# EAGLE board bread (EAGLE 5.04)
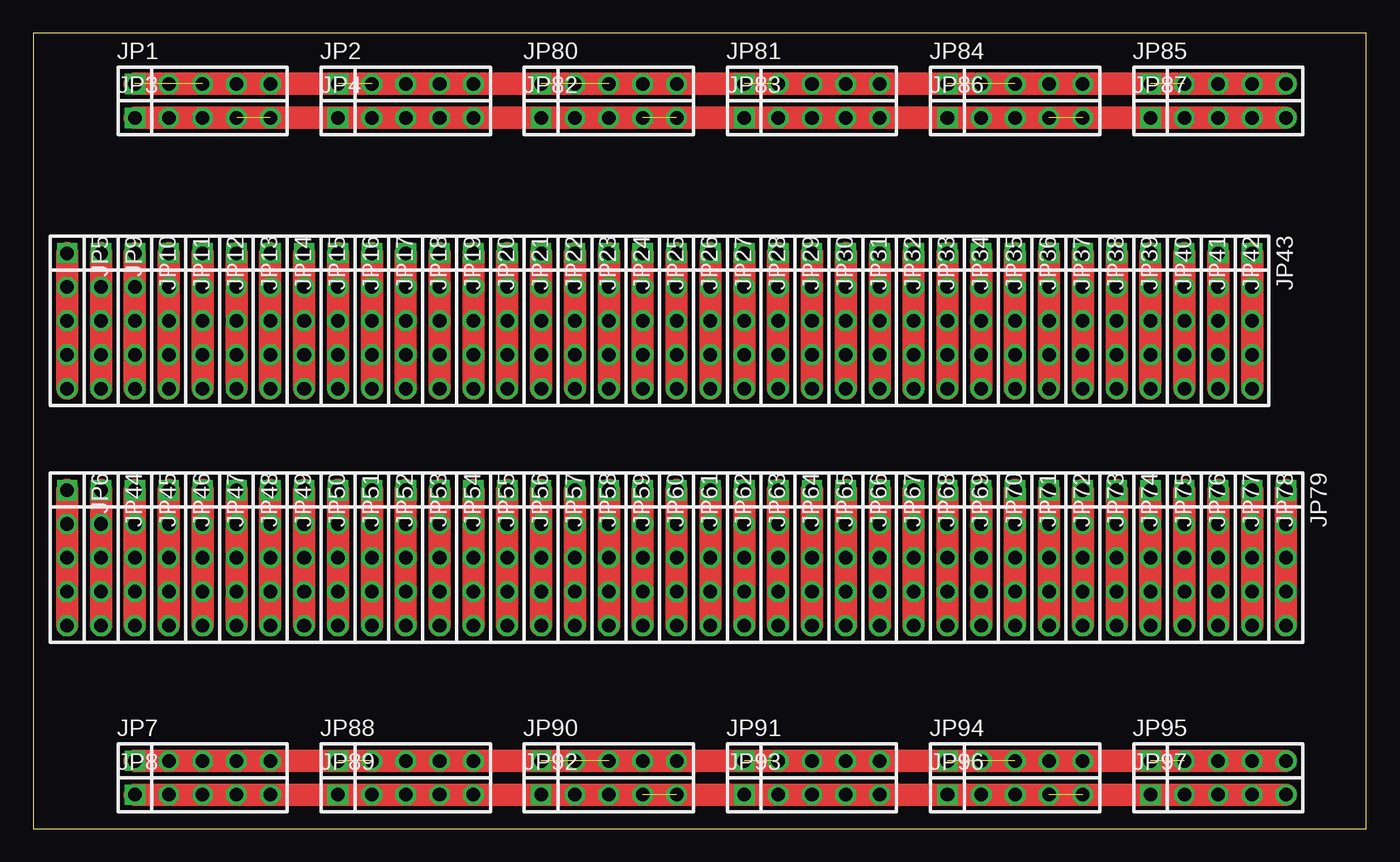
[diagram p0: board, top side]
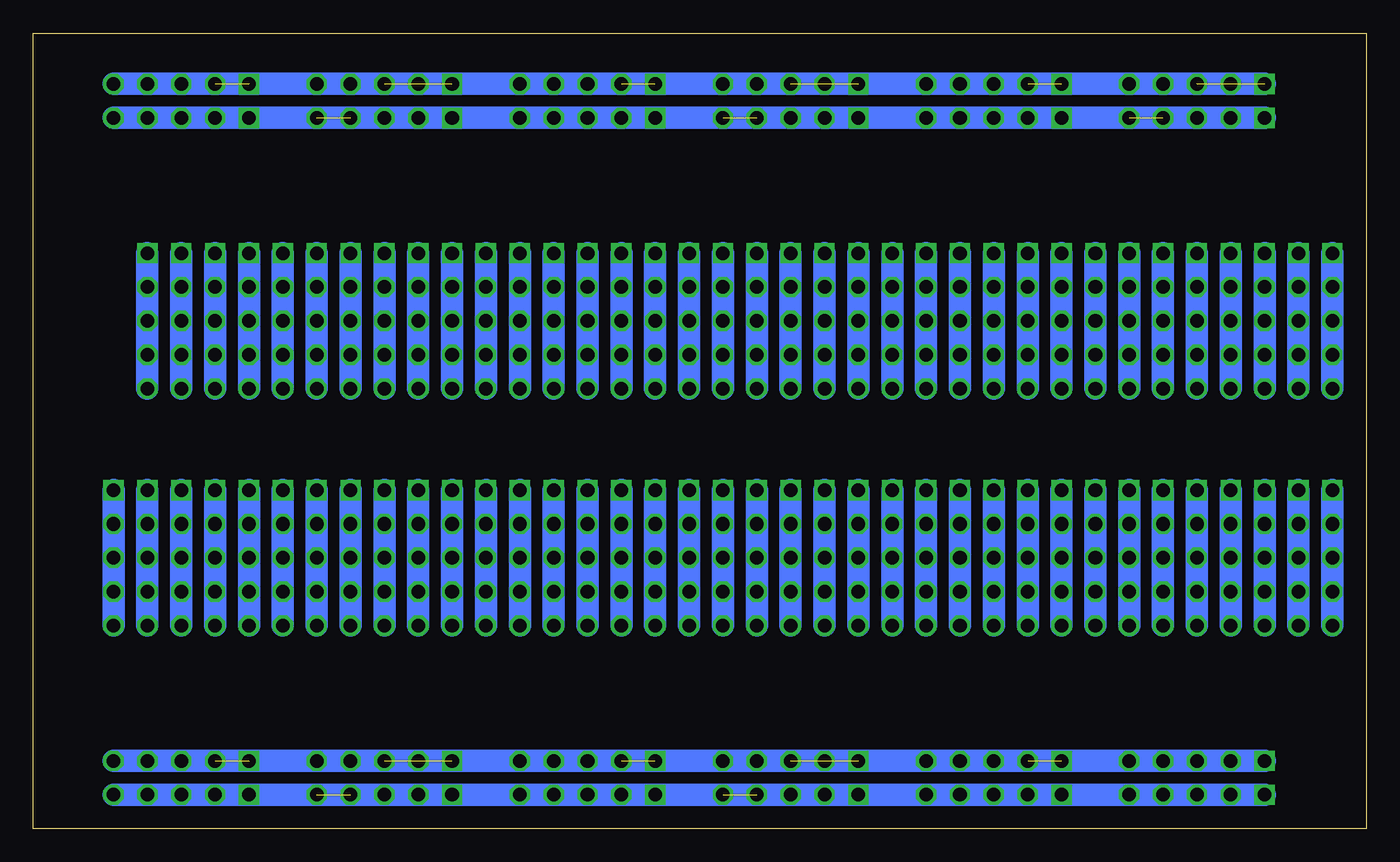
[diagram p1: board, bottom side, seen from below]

Size 100 x 59.68 mm. Coordinates in mm from the lower left corner, seen from the top.
Outline: 0,0 100,0 100,59.68 0,59.68 0,0
Copper layers (1*16): Top 0.035mm / dielectric 1.5mm / Bottom 0.035mm
Design rules "default": minimum track width 10mil, minimum drill 24mil, track to track 8mil, track to pad 8mil, pad to pad 8mil, via to via 8mil, smd to smd 8mil, copper to edge 40mil, drill to drill 8mil, minimum pad ring 10mil, minimum via ring 8mil, stop-mask expansion 4mil, vias tented up to drill 0mil, thermal gap 10mil

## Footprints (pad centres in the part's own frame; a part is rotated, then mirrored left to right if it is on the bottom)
1X05 = drill 1.016 square: 1 -5.08,0 | drill 1.016 octagon: 2 -2.54,0; 3 0,0; 4 2.54,0; 5 5.08,0

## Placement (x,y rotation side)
JP1  [1X05]  12.7,55.88 0 top
JP2  [1X05]  27.94,55.88 0 top
JP3  [1X05]  12.7,53.34 0 top
JP4  [1X05]  27.94,53.34 0 top
JP5  [1X05]  2.54,38.1 270 top
JP6  [1X05]  2.54,20.32 270 top
JP7  [1X05]  12.7,5.08 0 top
JP8  [1X05]  12.7,2.54 0 top
JP9  [1X05]  5.08,38.1 270 top
JP10  [1X05]  7.62,38.1 270 top
JP11  [1X05]  10.16,38.1 270 top
JP12  [1X05]  12.7,38.1 270 top
JP13  [1X05]  15.24,38.1 270 top
JP14  [1X05]  17.78,38.1 270 top
JP15  [1X05]  20.32,38.1 270 top
JP16  [1X05]  22.86,38.1 270 top
JP17  [1X05]  25.4,38.1 270 top
JP18  [1X05]  27.94,38.1 270 top
JP19  [1X05]  30.48,38.1 270 top
JP20  [1X05]  33.02,38.1 270 top
JP21  [1X05]  35.56,38.1 270 top
JP22  [1X05]  38.1,38.1 270 top
JP23  [1X05]  40.64,38.1 270 top
JP24  [1X05]  43.18,38.1 270 top
JP25  [1X05]  45.72,38.1 270 top
JP26  [1X05]  48.26,38.1 270 top
JP27  [1X05]  50.8,38.1 270 top
JP28  [1X05]  53.34,38.1 270 top
JP29  [1X05]  55.88,38.1 270 top
JP30  [1X05]  58.42,38.1 270 top
JP31  [1X05]  60.96,38.1 270 top
JP32  [1X05]  63.5,38.1 270 top
JP33  [1X05]  66.04,38.1 270 top
JP34  [1X05]  68.58,38.1 270 top
JP35  [1X05]  71.12,38.1 270 top
JP36  [1X05]  73.66,38.1 270 top
JP37  [1X05]  76.2,38.1 270 top
JP38  [1X05]  78.74,38.1 270 top
JP39  [1X05]  81.28,38.1 270 top
JP40  [1X05]  83.82,38.1 270 top
JP41  [1X05]  86.36,38.1 270 top
JP42  [1X05]  88.9,38.1 270 top
JP43  [1X05]  91.44,38.1 270 top
JP44  [1X05]  5.08,20.32 270 top
JP45  [1X05]  7.62,20.32 270 top
JP46  [1X05]  10.16,20.32 270 top
JP47  [1X05]  12.7,20.32 270 top
JP48  [1X05]  15.24,20.32 270 top
JP49  [1X05]  17.78,20.32 270 top
JP50  [1X05]  20.32,20.32 270 top
JP51  [1X05]  22.86,20.32 270 top
JP52  [1X05]  25.4,20.32 270 top
JP53  [1X05]  27.94,20.32 270 top
JP54  [1X05]  30.48,20.32 270 top
JP55  [1X05]  33.02,20.32 270 top
JP56  [1X05]  35.56,20.32 270 top
JP57  [1X05]  38.1,20.32 270 top
JP58  [1X05]  40.64,20.32 270 top
JP59  [1X05]  43.18,20.32 270 top
JP60  [1X05]  45.72,20.32 270 top
JP61  [1X05]  48.26,20.32 270 top
JP62  [1X05]  50.8,20.32 270 top
JP63  [1X05]  53.34,20.32 270 top
JP64  [1X05]  55.88,20.32 270 top
JP65  [1X05]  58.42,20.32 270 top
JP66  [1X05]  60.96,20.32 270 top
JP67  [1X05]  63.5,20.32 270 top
JP68  [1X05]  66.04,20.32 270 top
JP69  [1X05]  68.58,20.32 270 top
JP70  [1X05]  71.12,20.32 270 top
JP71  [1X05]  73.66,20.32 270 top
JP72  [1X05]  76.2,20.32 270 top
JP73  [1X05]  78.74,20.32 270 top
JP74  [1X05]  81.28,20.32 270 top
JP75  [1X05]  83.82,20.32 270 top
JP76  [1X05]  86.36,20.32 270 top
JP77  [1X05]  88.9,20.32 270 top
JP78  [1X05]  91.44,20.32 270 top
JP79  [1X05]  93.98,20.32 270 top
JP80  [1X05]  43.18,55.88 0 top
JP81  [1X05]  58.42,55.88 0 top
JP82  [1X05]  43.18,53.34 0 top
JP83  [1X05]  58.42,53.34 0 top
JP84  [1X05]  73.66,55.88 0 top
JP85  [1X05]  88.9,55.88 0 top
JP86  [1X05]  73.66,53.34 0 top
JP87  [1X05]  88.9,53.34 0 top
JP88  [1X05]  27.94,5.08 0 top
JP89  [1X05]  27.94,2.54 0 top
JP90  [1X05]  43.18,5.08 0 top
JP91  [1X05]  58.42,5.08 0 top
JP92  [1X05]  43.18,2.54 0 top
JP93  [1X05]  58.42,2.54 0 top
JP94  [1X05]  73.66,5.08 0 top
JP95  [1X05]  88.9,5.08 0 top
JP96  [1X05]  73.66,2.54 0 top
JP97  [1X05]  88.9,2.54 0 top

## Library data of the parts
JP1-JP97 = pinhead(2)

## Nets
N$1: JP1.1 JP1.2 JP1.3
N$2: JP2.1 JP2.2
N$3: JP3.4 JP3.5
N$76: JP80.1 JP80.2 JP80.3
N$77: JP81.1 JP81.2
N$78: JP82.4 JP82.5
N$80: JP84.1 JP84.2 JP84.3
N$81: JP85.1 JP85.2
N$82: JP86.4 JP86.5
N$84: JP88.1 JP88.2
N$86: JP90.1 JP90.2 JP90.3
N$87: JP91.1 JP91.2
N$88: JP92.4 JP92.5
N$90: JP94.1 JP94.2 JP94.3
N$91: JP95.1 JP95.2
N$92: JP96.4 JP96.5

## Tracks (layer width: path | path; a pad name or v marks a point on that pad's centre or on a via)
N$1  (2 unrouted)
N$2  (1 unrouted)
N$3  (1 unrouted)
N$4
  Top 1.676: 2.54,33.02 2.54,43.18
N$5
  Top 1.676: 5.08,33.02 5.08,43.18
N$6
  Top 1.676: 7.62,33.02 7.62,43.18
N$7
  Top 1.676: 91.44,33.02 91.44,43.18
N$8
  Top 1.676: 88.9,33.02 88.9,43.18
N$9
  Top 1.676: 86.36,33.02 86.36,43.18
N$10
  Top 1.676: 83.82,33.02 83.82,43.18
N$11
  Top 1.676: 81.28,33.02 81.28,43.18
N$12
  Top 1.676: 78.74,33.02 78.74,43.18
N$13
  Top 1.676: 76.2,33.02 76.2,43.18
N$14
  Top 1.676: 73.66,33.02 73.66,43.18
N$15
  Top 1.676: 71.12,33.02 71.12,43.18
N$16
  Top 1.676: 68.58,33.02 68.58,43.18
N$17
  Top 1.676: 66.04,33.02 66.04,43.18
N$18
  Top 1.676: 63.5,33.02 63.5,43.18
N$19
  Top 1.676: 60.96,33.02 60.96,43.18
N$20
  Top 1.676: 58.42,33.02 58.42,43.18
N$21
  Top 1.676: 55.88,33.02 55.88,43.18
N$22
  Top 1.676: 53.34,33.02 53.34,43.18
N$23
  Top 1.676: 50.8,33.02 50.8,43.18
N$24
  Top 1.676: 48.26,33.02 48.26,43.18
N$25
  Top 1.676: 45.72,33.02 45.72,43.18
N$26
  Top 1.676: 43.18,33.02 43.18,43.18
N$27
  Top 1.676: 40.64,33.02 40.64,43.18
N$28
  Top 1.676: 38.1,33.02 38.1,43.18
N$29
  Top 1.676: 35.56,33.02 35.56,43.18
N$30
  Top 1.676: 33.02,33.02 33.02,43.18
N$31
  Top 1.676: 30.48,33.02 30.48,43.18
N$32
  Top 1.676: 27.94,33.02 27.94,43.18
N$33
  Top 1.676: 25.4,33.02 25.4,43.18
N$34
  Top 1.676: 22.86,33.02 22.86,43.18
N$35
  Top 1.676: 20.32,33.02 20.32,43.18
N$36
  Top 1.676: 17.78,33.02 17.78,43.18
N$37
  Top 1.676: 15.24,33.02 15.24,43.18
N$38
  Top 1.676: 12.7,33.02 12.7,43.18
N$39
  Top 1.676: 10.16,33.02 10.16,43.18
N$40
  Top 1.676: 5.08,15.24 5.08,25.4 | 93.98,55.88 83.82,55.88 | 83.82,53.34 93.98,53.34 | 68.58,53.34 78.74,53.34 | 78.74,55.88 68.58,55.88 | 2.54,25.4 2.54,15.24
N$41
  Top 1.676: 93.98,15.24 93.98,25.4
N$42
  Top 1.676: 91.44,15.24 91.44,25.4
N$43
  Top 1.676: 88.9,15.24 88.9,25.4
N$44
  Top 1.676: 86.36,15.24 86.36,25.4
N$45
  Top 1.676: 83.82,15.24 83.82,25.4
N$46
  Top 1.676: 81.28,15.24 81.28,25.4
N$47
  Top 1.676: 78.74,15.24 78.74,25.4
N$48
  Top 1.676: 76.2,15.24 76.2,25.4
N$49
  Top 1.676: 73.66,15.24 73.66,25.4
N$50
  Top 1.676: 71.12,15.24 71.12,25.4
N$51
  Top 1.676: 68.58,15.24 68.58,25.4
N$52
  Top 1.676: 66.04,15.24 66.04,25.4
N$53
  Top 1.676: 63.5,15.24 63.5,25.4
N$54
  Top 1.676: 60.96,15.24 60.96,25.4
N$55
  Top 1.676: 58.42,15.24 58.42,25.4
N$56
  Top 1.676: 55.88,15.24 55.88,25.4
N$57
  Top 1.676: 53.34,15.24 53.34,25.4
N$58
  Top 1.676: 50.8,15.24 50.8,25.4
N$59
  Top 1.676: 48.26,15.24 48.26,25.4
N$60
  Top 1.676: 45.72,15.24 45.72,25.4
N$61
  Top 1.676: 43.18,15.24 43.18,25.4
N$62
  Top 1.676: 40.64,15.24 40.64,25.4
N$63
  Top 1.676: 38.1,15.24 38.1,25.4
N$64
  Top 1.676: 35.56,15.24 35.56,25.4
N$65
  Top 1.676: 33.02,15.24 33.02,25.4
N$66
  Top 1.676: 30.48,15.24 30.48,25.4
N$67
  Top 1.676: 27.94,15.24 27.94,25.4
N$68
  Top 1.676: 25.4,15.24 25.4,25.4
N$69
  Top 1.676: 22.86,15.24 22.86,25.4
N$70
  Top 1.676: 20.32,15.24 20.32,25.4
N$71
  Top 1.676: 17.78,15.24 17.78,25.4
N$72
  Top 1.676: 15.24,15.24 15.24,25.4
N$73
  Top 1.676: 12.7,15.24 12.7,25.4
N$74
  Top 1.676: 10.16,15.24 10.16,25.4
N$75
  Top 1.676: 7.62,15.24 7.62,25.4
N$76  (2 unrouted)
N$77  (1 unrouted)
N$78  (1 unrouted)
N$79
  Top 1.676: 63.5,55.88 53.34,55.88 | 53.34,53.34 63.5,53.34 | 38.1,53.34 48.26,53.34 | 48.26,55.88 38.1,55.88
N$80  (2 unrouted)
N$81  (1 unrouted)
N$82  (1 unrouted)
N$83
  Top 1.676: 33.02,55.88 22.86,55.88 | 22.86,53.34 33.02,53.34 | 7.62,53.34 17.78,53.34 | 17.78,55.88 7.62,55.88
N$84  (1 unrouted)
N$85
  Top 1.676: 68.58,2.54 78.74,2.54 | 78.74,5.08 68.58,5.08 | 93.98,5.08 83.82,5.08 | 83.82,2.54 93.98,2.54
N$86  (2 unrouted)
N$87  (1 unrouted)
N$88  (1 unrouted)
N$89
  Top 1.676: 63.5,5.08 53.34,5.08 | 53.34,2.54 63.5,2.54 | 38.1,2.54 48.26,2.54 | 48.26,5.08 38.1,5.08
N$90  (2 unrouted)
N$91  (1 unrouted)
N$92  (1 unrouted)
N$93
  Top 1.676: 33.02,5.08 22.86,5.08 | 22.86,2.54 33.02,2.54 | 7.62,2.54 17.78,2.54 | 17.78,5.08 7.62,5.08
N$94
  Bottom 1.676: 2.54,33.02 2.54,43.18
N$95
  Bottom 1.676: 5.08,33.02 5.08,43.18
N$96
  Bottom 1.676: 7.62,33.02 7.62,43.18
N$97
  Bottom 1.676: 10.16,33.02 10.16,43.18
N$98
  Bottom 1.676: 12.7,33.02 12.7,43.18
N$99
  Bottom 1.676: 15.24,33.02 15.24,43.18
N$100
  Bottom 1.676: 17.78,33.02 17.78,43.18
N$101
  Bottom 1.676: 20.32,33.02 20.32,43.18
N$102
  Bottom 1.676: 22.86,33.02 22.86,43.18
N$103
  Bottom 1.676: 25.4,33.02 25.4,43.18
N$104
  Bottom 1.676: 27.94,33.02 27.94,43.18
N$105
  Bottom 1.676: 30.48,33.02 30.48,43.18
N$106
  Bottom 1.676: 33.02,33.02 33.02,43.18
N$107
  Bottom 1.676: 35.56,33.02 35.56,43.18
N$108
  Bottom 1.676: 38.1,33.02 38.1,43.18
N$109
  Bottom 1.676: 40.64,33.02 40.64,43.18
N$110
  Bottom 1.676: 43.18,33.02 43.18,43.18
N$111
  Bottom 1.676: 45.72,33.02 45.72,43.18
N$112
  Bottom 1.676: 48.26,33.02 48.26,43.18
N$113
  Bottom 1.676: 50.8,33.02 50.8,43.18
N$114
  Bottom 1.676: 53.34,33.02 53.34,43.18
N$115
  Bottom 1.676: 55.88,33.02 55.88,43.18
N$116
  Bottom 1.676: 58.42,33.02 58.42,43.18
N$117
  Bottom 1.676: 60.96,33.02 60.96,43.18
N$118
  Bottom 1.676: 63.5,33.02 63.5,43.18
N$119
  Bottom 1.676: 66.04,33.02 66.04,43.18
N$120
  Bottom 1.676: 68.58,33.02 68.58,43.18
N$121
  Bottom 1.676: 71.12,33.02 71.12,43.18
N$122
  Bottom 1.676: 73.66,33.02 73.66,43.18
N$123
  Bottom 1.676: 76.2,33.02 76.2,43.18
N$124
  Bottom 1.676: 78.74,33.02 78.74,43.18
N$125
  Bottom 1.676: 81.28,33.02 81.28,43.18
N$126
  Bottom 1.676: 83.82,33.02 83.82,43.18
N$127
  Bottom 1.676: 86.36,33.02 86.36,43.18
N$128
  Bottom 1.676: 88.9,33.02 88.9,43.18
N$129
  Bottom 1.676: 91.44,33.02 91.44,43.18
N$130
  Bottom 1.676: 5.08,15.24 5.08,25.4 | 7.62,55.88 17.78,55.88 | 17.78,53.34 7.62,53.34 | 33.02,53.34 22.86,53.34 | 22.86,55.88 33.02,55.88 | 2.54,25.4 2.54,15.24
N$131
  Bottom 1.676: 7.62,15.24 7.62,25.4
N$132
  Bottom 1.676: 10.16,15.24 10.16,25.4
N$133
  Bottom 1.676: 12.7,15.24 12.7,25.4
N$134
  Bottom 1.676: 15.24,15.24 15.24,25.4
N$135
  Bottom 1.676: 17.78,15.24 17.78,25.4
N$136
  Bottom 1.676: 20.32,15.24 20.32,25.4
N$137
  Bottom 1.676: 22.86,15.24 22.86,25.4
N$138
  Bottom 1.676: 25.4,15.24 25.4,25.4
N$139
  Bottom 1.676: 27.94,15.24 27.94,25.4
N$140
  Bottom 1.676: 30.48,15.24 30.48,25.4
N$141
  Bottom 1.676: 33.02,15.24 33.02,25.4
N$142
  Bottom 1.676: 35.56,15.24 35.56,25.4
N$143
  Bottom 1.676: 38.1,15.24 38.1,25.4
N$144
  Bottom 1.676: 40.64,15.24 40.64,25.4
N$145
  Bottom 1.676: 43.18,15.24 43.18,25.4
N$146
  Bottom 1.676: 45.72,15.24 45.72,25.4
N$147
  Bottom 1.676: 48.26,15.24 48.26,25.4
N$148
  Bottom 1.676: 50.8,15.24 50.8,25.4
N$149
  Bottom 1.676: 53.34,15.24 53.34,25.4
N$150
  Bottom 1.676: 55.88,15.24 55.88,25.4
N$151
  Bottom 1.676: 58.42,15.24 58.42,25.4
N$152
  Bottom 1.676: 60.96,15.24 60.96,25.4
N$153
  Bottom 1.676: 63.5,15.24 63.5,25.4
N$154
  Bottom 1.676: 66.04,15.24 66.04,25.4
N$155
  Bottom 1.676: 68.58,15.24 68.58,25.4
N$156
  Bottom 1.676: 71.12,15.24 71.12,25.4
N$157
  Bottom 1.676: 73.66,15.24 73.66,25.4
N$158
  Bottom 1.676: 76.2,15.24 76.2,25.4
N$159
  Bottom 1.676: 78.74,15.24 78.74,25.4
N$160
  Bottom 1.676: 81.28,15.24 81.28,25.4
N$161
  Bottom 1.676: 83.82,15.24 83.82,25.4
N$162
  Bottom 1.676: 86.36,15.24 86.36,25.4
N$163
  Bottom 1.676: 88.9,15.24 88.9,25.4
N$164
  Bottom 1.676: 91.44,15.24 91.44,25.4
N$165
  Bottom 1.676: 93.98,15.24 93.98,25.4
N$166
  Bottom 1.676: 38.1,55.88 48.26,55.88 | 48.26,53.34 38.1,53.34 | 63.5,53.34 53.34,53.34 | 53.34,55.88 63.5,55.88
N$167
  Bottom 1.676: 68.58,55.88 78.74,55.88 | 78.74,53.34 68.58,53.34 | 93.98,53.34 83.82,53.34 | 83.82,55.88 93.98,55.88
N$168
  Bottom 1.676: 33.02,2.54 22.86,2.54 | 22.86,5.08 33.02,5.08 | 7.62,5.08 17.78,5.08 | 17.78,2.54 7.62,2.54
N$169
  Bottom 1.676: 38.1,5.08 48.26,5.08 | 48.26,2.54 38.1,2.54 | 63.5,2.54 53.34,2.54 | 53.34,5.08 63.5,5.08
N$170
  Bottom 1.676: 68.58,5.08 78.74,5.08 | 78.74,2.54 68.58,2.54 | 93.98,2.54 83.82,2.54 | 83.82,5.08 93.98,5.08
S$1
  Top 1.676: 83.82,55.88 78.74,55.88
S$2
  Top 1.676: 83.82,53.34 78.74,53.34
S$3
  Top 1.676: 53.34,55.88 48.26,55.88 | 68.58,55.88 63.5,55.88
S$4
  Top 1.676: 53.34,53.34 48.26,53.34 | 68.58,53.34 63.5,53.34
S$5
  Top 1.676: 22.86,55.88 17.78,55.88 | 38.1,55.88 33.02,55.88
S$6
  Top 1.676: 22.86,53.34 17.78,53.34 | 38.1,53.34 33.02,53.34
S$7
  Top 1.676: 83.82,5.08 78.74,5.08
S$8
  Top 1.676: 83.82,2.54 78.74,2.54
S$9
  Top 1.676: 53.34,5.08 48.26,5.08 | 68.58,5.08 63.5,5.08
S$10
  Top 1.676: 53.34,2.54 48.26,2.54 | 68.58,2.54 63.5,2.54
S$11
  Top 1.676: 22.86,5.08 17.78,5.08 | 38.1,5.08 33.02,5.08
S$12
  Top 1.676: 22.86,2.54 17.78,2.54 | 38.1,2.54 33.02,2.54
S$13
  Bottom 1.676: 17.78,55.88 22.86,55.88
S$14
  Bottom 1.676: 17.78,53.34 22.86,53.34
S$15
  Bottom 1.676: 48.26,55.88 53.34,55.88 | 33.02,55.88 38.1,55.88
S$16
  Bottom 1.676: 48.26,53.34 53.34,53.34 | 33.02,53.34 38.1,53.34
S$17
  Bottom 1.676: 78.74,55.88 83.82,55.88 | 63.5,55.88 68.58,55.88
S$18
  Bottom 1.676: 78.74,53.34 83.82,53.34 | 63.5,53.34 68.58,53.34
S$19
  Bottom 1.676: 17.78,5.08 22.86,5.08
S$20
  Bottom 1.676: 17.78,2.54 22.86,2.54
S$21
  Bottom 1.676: 48.26,5.08 53.34,5.08 | 33.02,5.08 38.1,5.08
S$22
  Bottom 1.676: 48.26,2.54 53.34,2.54 | 33.02,2.54 38.1,2.54
S$23
  Bottom 1.676: 78.74,5.08 83.82,5.08 | 63.5,5.08 68.58,5.08
S$24
  Bottom 1.676: 78.74,2.54 83.82,2.54 | 63.5,2.54 68.58,2.54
